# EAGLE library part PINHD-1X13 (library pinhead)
PIN HEADER
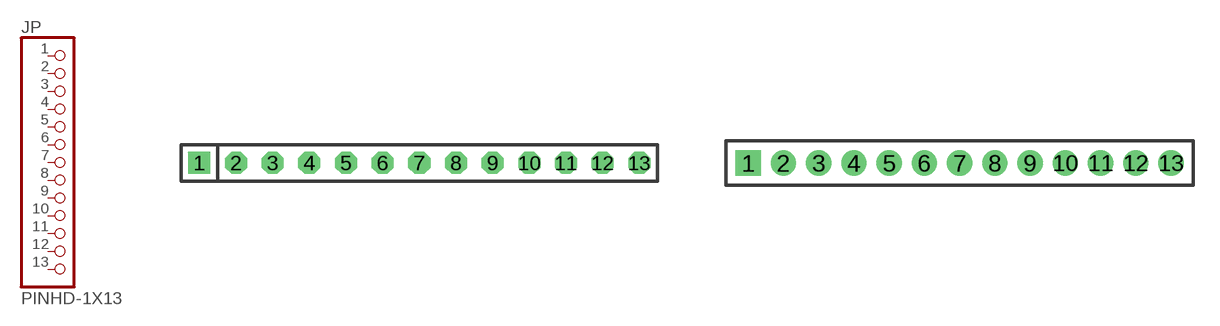
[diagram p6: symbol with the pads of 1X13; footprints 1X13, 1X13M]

Designator prefix JP

## PINHD-1X13  [1X13]
1  1  pas
2  2  pas
3  3  pas
4  4  pas
5  5  pas
6  6  pas
7  7  pas
8  8  pas
9  9  pas
10  10  pas
11  11  pas
12  12  pas
13  13  pas

## PINHD-1X13M  [1X13M]
Pads as for 1X13

## Footprint 1X13 (pad centres in mm)
PIN HEADER - 0.1"
drill 1.016 square: 1 -15.24,0
drill 1.016 octagon: 2 -12.7,0; 3 -10.16,0; 4 -7.62,0; 5 -5.08,0; 6 -2.54,0; 7 0,0; 8 2.54,0; 9 5.08,0; 10 7.62,0; 11 10.16,0; 12 12.7,0; 13 15.24,0

## Footprint 1X13M (pad centres in mm)
PIN HEADER - 2MM"
drill 0.914 square: 1 -12,0
drill 0.914 round: 2 -10,0; 3 -8,0; 4 -6,0; 5 -4,0; 6 -2,0; 7 0,0; 8 2,0; 9 4,0; 10 6,0; 11 8,0; 12 10,0; 13 12,0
